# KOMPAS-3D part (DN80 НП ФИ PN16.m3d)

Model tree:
1. Операция без истории:1

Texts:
  DN80 НП ФИ PN16
  133 1 134 1 135 1 136 0 50 1|SPDS|133 1 134 1 135 1 136 0 50 1
  125 1 126 1 127 1 128 0 50 1|SPDS|125 1 126 1 127 1 128 0 50 1
  129 1 130 1 131 1 132 0 50 1|SPDS|129 1 130 1 131 1 132 0 50 1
